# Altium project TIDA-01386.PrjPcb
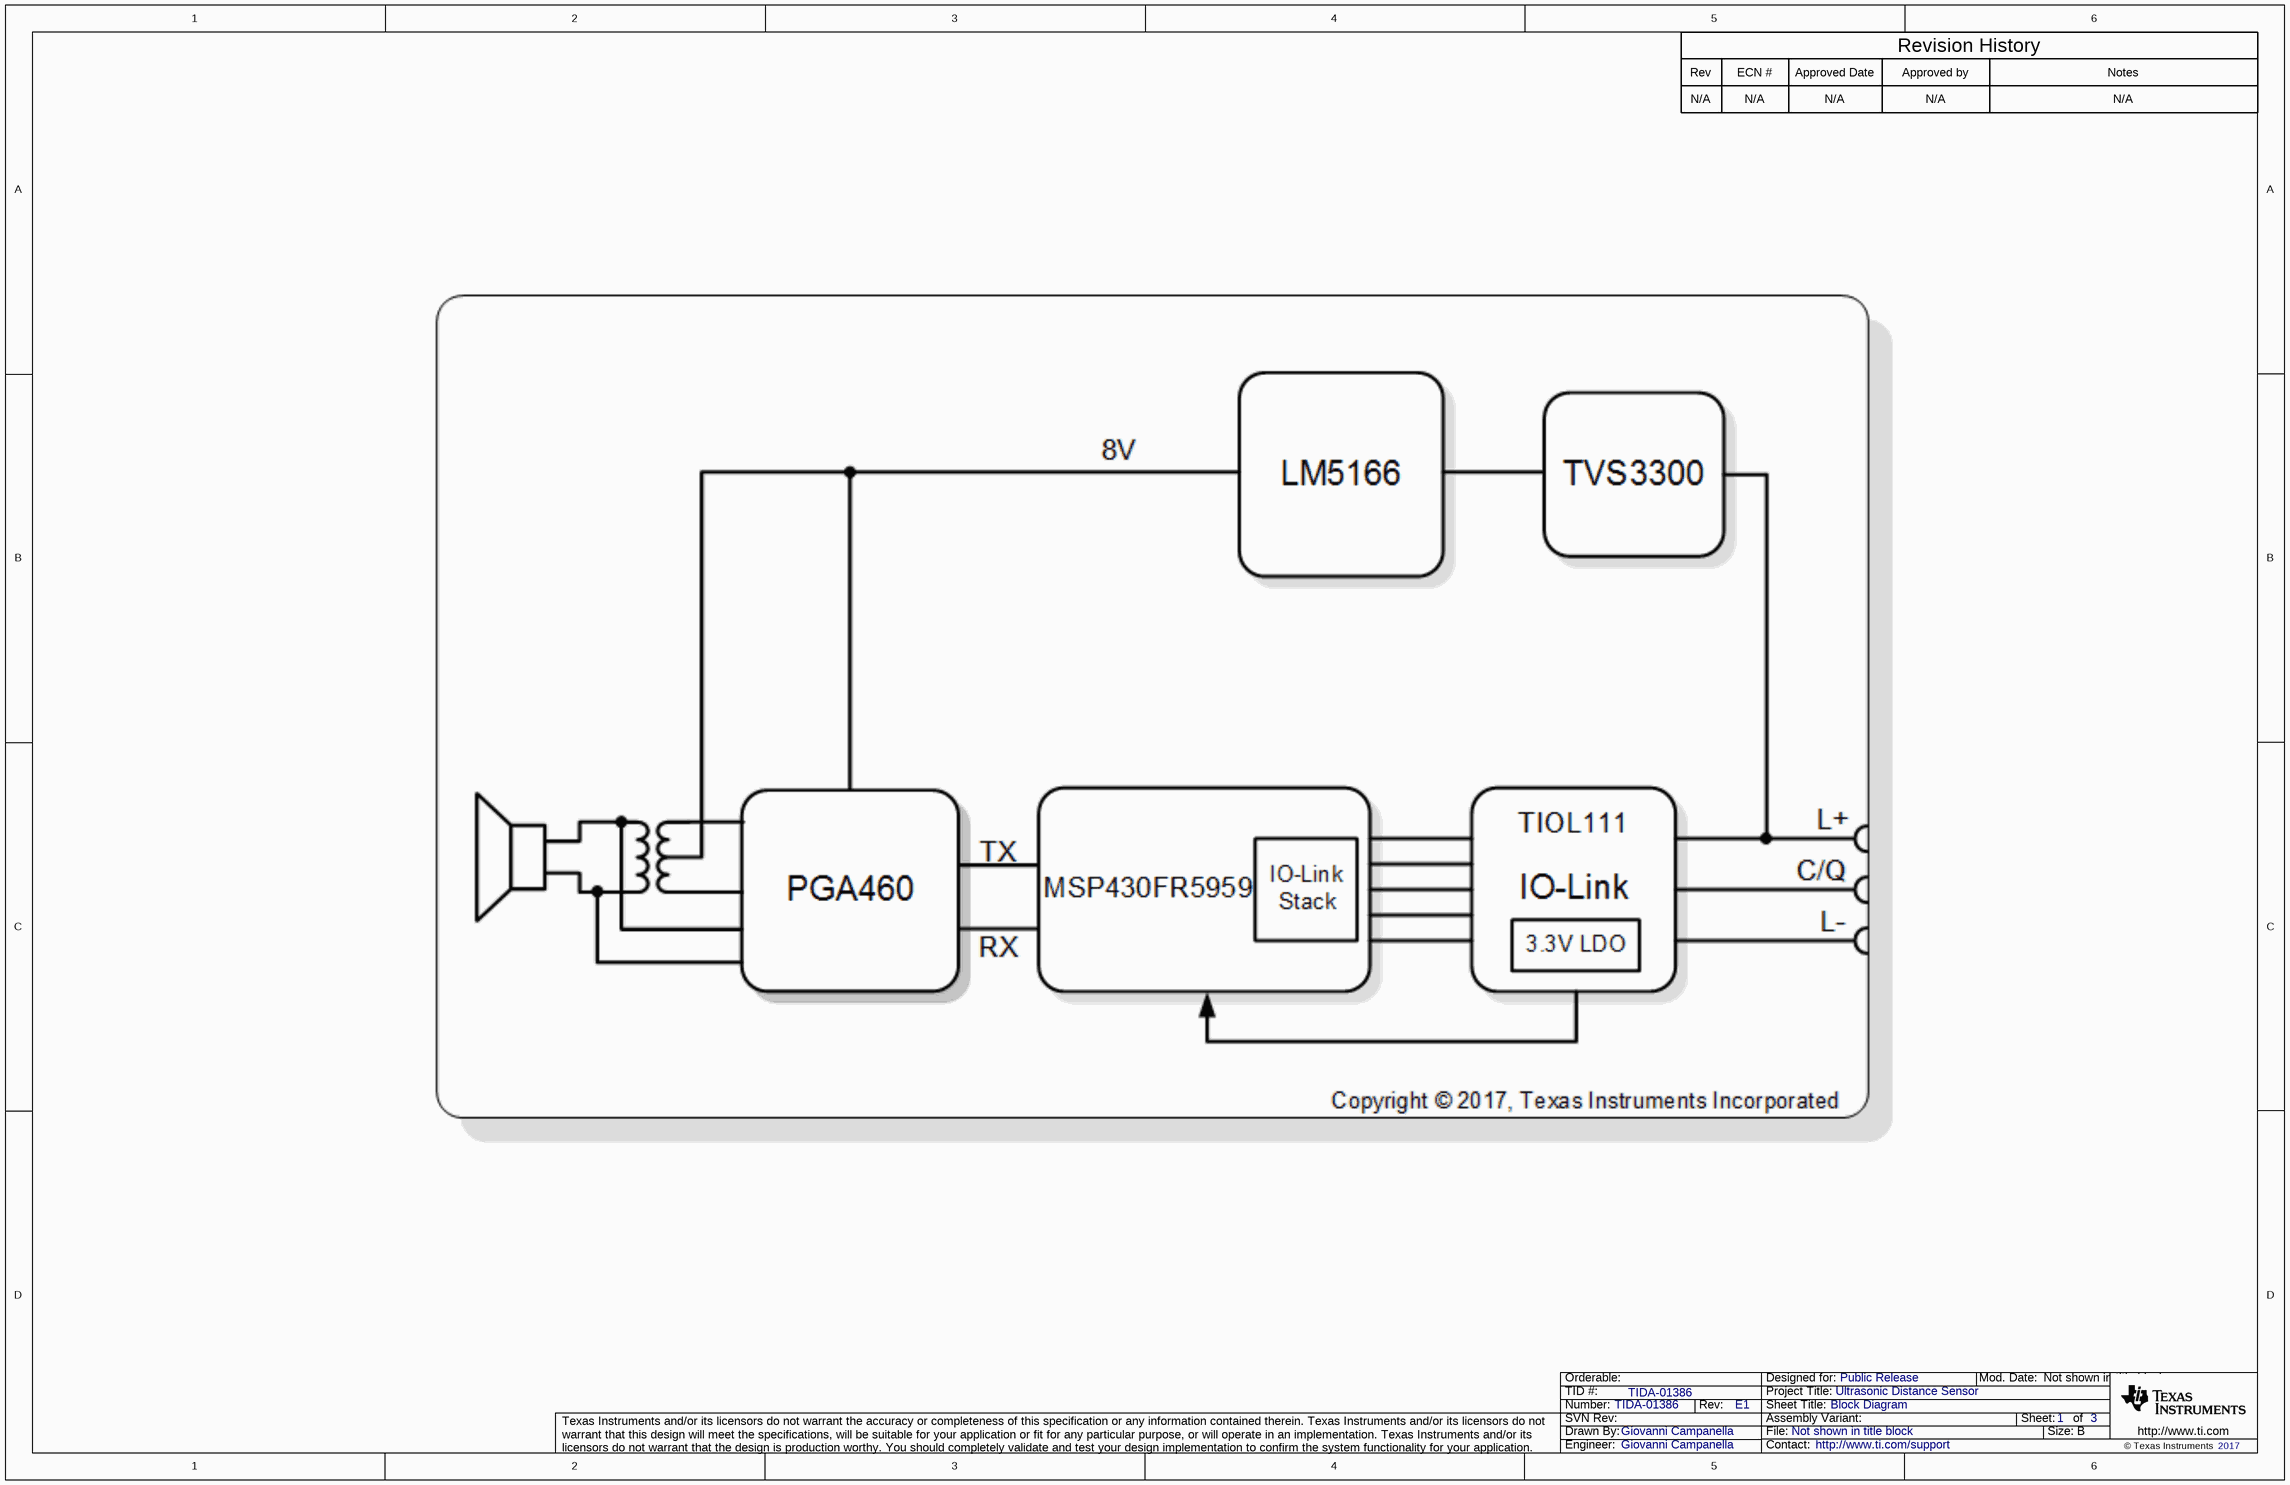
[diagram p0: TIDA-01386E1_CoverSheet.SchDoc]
TID: TIDA-01386; TechSupport: http://www.ti.com/support; SCH_Rev: E1; PRJ_Title: Ultrasonic Distance Sensor; PRJ_Number: TIDA-01386; PRJ_Engineer: Giovanni Campanella; PRJ_Customer: Public Release; PCB_Rev: E1; PCB_Layout: GCD; CopyrightYear: 2017
3 sheets, 68 parts. Net scope: flat (ports and power ports of the same name join across sheets).
Board file: TIDA-01386E1_PCB.PcbDoc
Sheets:
  TIDA-01386E1_CoverSheet.SchDoc
  TIDA-01386E1_Schematic.SchDoc
  TIDA-01386E1_Hardware.SchDoc

## Sheet TIDA-01386E1_CoverSheet.SchDoc: Block Diagram
size 431 x 279 mm; Date: Not shown in title block; ApprovedBy: Not shown in title block; CheckedBy: Not shown in title block; Author: Not shown in title block; CompanyName: Not shown in title block; DrawnBy: Giovanni Campanella; Engineer: Not shown in title block; Organization: Not shown in title block; Address1: Not shown in title block; Address2: Not shown in title block; Address3: Not shown in title block; Address4: Not shown in title block; DocumentNumber: 1; Revision: Use project parameter SCH_Rev; SheetNumber: 1; SheetTotal: 3; PageSetup: Record=PageOptions¦CenterHorizontal=True¦CenterVertical=True¦PrintScale=1.00¦XCorrection=1.00¦YCorrection=1.00¦PrintKind=0¦BorderSize=5000000¦LeftOffset=0¦BottomOffset=0¦Orientation=2¦PaperLength=1000¦PaperWidth=1000¦Scale=100¦PaperSource=15¦PrintQuality=600¦MediaType=1¦DitherType=10¦PaperKind=Letter¦PrintScaleMode=1

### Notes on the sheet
- Rev
- N/A
- ECN #
- Approved Date
- Approved by
- Revision History
- Notes

## Sheet TIDA-01386E1_Schematic.SchDoc: Schematic
size 431 x 279 mm; Date: Not shown in title block; ApprovedBy: Not shown in title block; CheckedBy: Not shown in title block; Author: Not shown in title block; CompanyName: Not shown in title block; DrawnBy: Giovanni Campanella; Engineer: Not shown in title block; Organization: Not shown in title block; Address1: Not shown in title block; Address2: Not shown in title block; Address3: Not shown in title block; Address4: Not shown in title block; DocumentNumber: 1; Revision: Use project parameter SCH_Rev; SheetNumber: 2; SheetTotal: 3; PageSetup: Record=PageOptions¦CenterHorizontal=True¦CenterVertical=True¦PrintScale=1.00¦XCorrection=1.00¦YCorrection=1.00¦PrintKind=0¦BorderSize=5000000¦LeftOffset=0¦BottomOffset=0¦Orientation=2¦PaperLength=1000¦PaperWidth=1000¦Scale=100¦PaperSource=15¦PrintQuality=600¦MediaType=1¦DitherType=10¦PaperKind=Letter¦PrintScaleMode=1
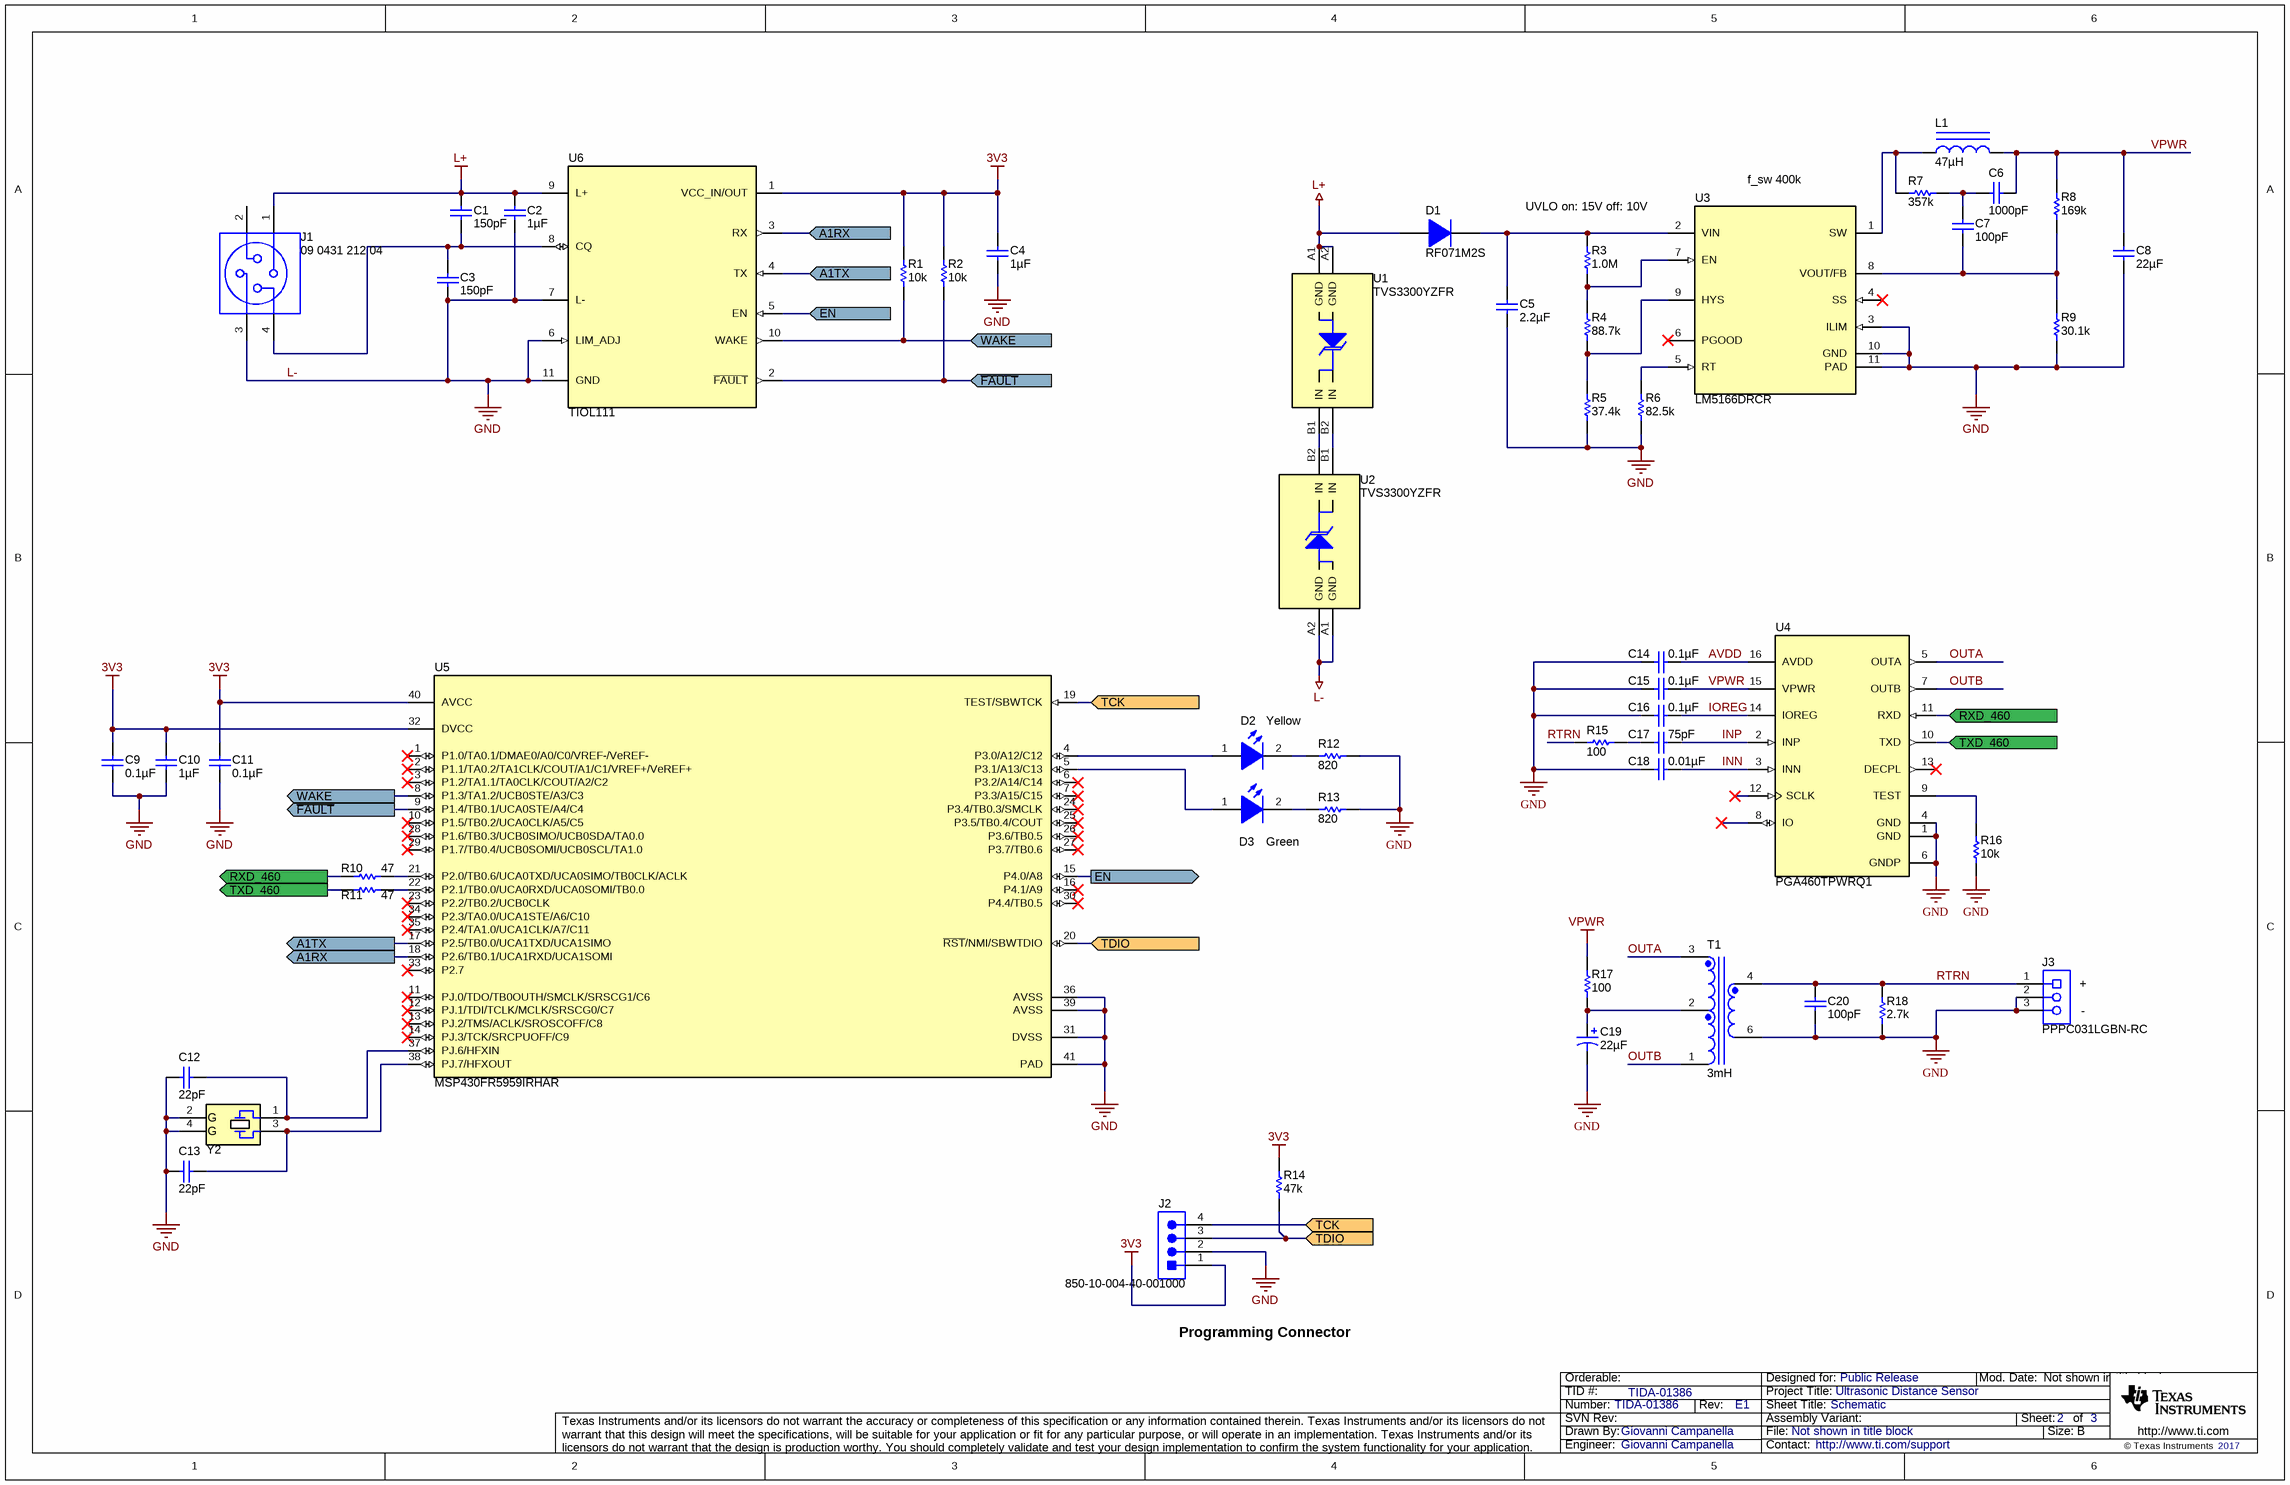
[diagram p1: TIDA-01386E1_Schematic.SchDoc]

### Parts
C1  ValueDisplayed: 150pF  [0402]  (hidden comment: 885012005062)
C2  ValueDisplayed: 1µF  [0805_HV1]  (hidden comment: CGA4J3X7S2A105K125AB)
C3  ValueDisplayed: 150pF  [0402]  (hidden comment: 885012005062)
C4  ValueDisplayed: 1µF  [0402]  (hidden comment: 885012105012)
C5  ValueDisplayed: 2.2µF  [1206_180]  (hidden comment: C3216X7S2A225K160AB)
C6  ValueDisplayed: 1000pF  [0603]  (hidden comment: 885012206083)
C7  ValueDisplayed: 100pF  [0603]  (hidden comment: 885012006057)
C8  ValueDisplayed: 22µF  [0603]  (hidden comment: C1608X5R1A226M080AC)
C9  ValueDisplayed: 0.1µF  [0402]  (hidden comment: GRM155R71E104KE14D)
C10  ValueDisplayed: 1µF  [0402]  (hidden comment: 885012105012)
C11  ValueDisplayed: 0.1µF  [0402]  (hidden comment: GRM155R71E104KE14D)
C12  ValueDisplayed: 22pF  [0402]  (hidden comment: 885012005009)
C13  ValueDisplayed: 22pF  [0402]  (hidden comment: 885012005009)
C14  ValueDisplayed: 0.1µF  [0603]  (hidden comment: C1608X7R1H104K080AA)
C15  ValueDisplayed: 0.1µF  [0603]  (hidden comment: C1608X7R1H104K080AA)
C16  ValueDisplayed: 0.1µF  [0603]  (hidden comment: C1608X7R1H104K080AA)
C17  ValueDisplayed: 75pF  [0603]  (hidden comment: GRM1885C2A750JA01D)
C18  ValueDisplayed: 0.01µF  [0603]  (hidden comment: 06031C103JAT2A)
C19  ValueDisplayed: 22µF  [CAPSMT_62_E55]  (hidden comment: EMVA350ADA220ME55G)
C20  ValueDisplayed: 100pF  [0603]  (hidden comment: C1608C0G2A101F080AA)
D1  RF071M2S  [SOD-123]
D2  value Yellow  [LY L29K_Yellow]  (hidden comment: LY L29K-J1K2-26-Z)
D3  value Green  [LG L29K_GREEN]  (hidden comment: LG L29K-G2J1-24-Z)
J1  09 0431 212 04  [Binder_713_763_Edge_ENGR-ONLY]
J2  850-10-004-40-001000  [Mill-max_850-10-004-40-001000]
J3  PPPC031LGBN-RC  [Sullins_PPxC031LGBN-RC]
L1  ValueDisplayed: 47µH  [WE-PD2-S]  (hidden comment: 744773147)
R1  ValueDisplayed: 10k  [0402]  (hidden comment: CRCW040210K0JNED)
R2  ValueDisplayed: 10k  [0402]  (hidden comment: CRCW040210K0JNED)
R3  ValueDisplayed: 1.0M  [0402]  (hidden comment: CRCW04021M00JNED)
R4  ValueDisplayed: 88.7k  [0402]  (hidden comment: CRCW040288K7FKED)
R5  ValueDisplayed: 37.4k  [0402]  (hidden comment: CRCW040237K4FKED)
R6  ValueDisplayed: 82.5k  [0402]  (hidden comment: CRCW040282K5FKED)
R7  ValueDisplayed: 357k  [0402]  (hidden comment: CRCW0402357KFKED)
R8  ValueDisplayed: 169k  [0402]  (hidden comment: CRCW0402169KFKED)
R9  ValueDisplayed: 30.1k  [0402]  (hidden comment: CRCW040230K1FKED)
R10  ValueDisplayed: 47  [0402]  (hidden comment: MCR01MZPJ470)
R11  ValueDisplayed: 47  [0402]  (hidden comment: MCR01MZPJ470)
R12  ValueDisplayed: 820  [0402]  (hidden comment: CRCW0402820RJNED)
R13  ValueDisplayed: 820  [0402]  (hidden comment: CRCW0402820RJNED)
R14  value 47k  [0402S]  (hidden comment: CRCW040247K0JNED)
R15  ValueDisplayed: 100  [0603]  (hidden comment: CRCW0603100RFKEA)
R16  ValueDisplayed: 10k  [0402]  (hidden comment: CRCW040210K0JNED)
R17  ValueDisplayed: 100  [0402]  (hidden comment: CRCW0402100RFKED)
R18  ValueDisplayed: 2.7k  [0402]  (hidden comment: CRCW04022K70JNED)
T1  ValueDisplayed: 3mH  [TDK_B78416A2232A003]  (hidden comment: B78416A2232A003)
U1  TVS3300YZFR  [YZF0004-C01]
U2  TVS3300YZFR  [YZF0004-C01]
U3  LM5166DRCR  [DRC0010J]
U4  PGA460TPWRQ1  [PW0016A_N]
U5  MSP430FR5959IRHAR  [RHA0040B]
U6  TIOL111  [TIOL111]
Y2  ABM8-14.7456MHZ-10-1-U-T  [XTAL_ABM8]  (value not drawn)

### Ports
A1RX, A1TX, EN (in), EN (out), RXD_460, TCK, TDIO, TXD_460, WAKE, ~{FAULT}

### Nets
3V3: C4.1 C9.1 C10.1 C11.1 J2.1 R1.2 R2.2 R14.2 U5.32(DVCC) U5.40(AVCC) U6.1(VCC_IN/OUT)
L+: C1.1 C2.1 D1.2(A) J1.1 U1.A1(GND) U1.A2(GND) U6.9(L+)
L-: C2.2 C3.2 C4.2 C5.2 C8.2 C9.2 C10.2 C11.2 C12.2 C13.2 C14.2 C15.2 C16.2 C18.2 C19.2(-) C20.2 J1.3 J2.2 J3.2 J3.3 R5.1 R6.1 R9.1 R12.2 R13.2 R16.1 R18.1 T1.6 U2.A1(GND) U2.A2(GND) U3.3(ILIM) U3.10(GND) U3.11(PAD) U4.1(GND) U4.4(GND) U4.6(GNDP) U5.31(DVSS) U5.36(AVSS) U5.39(AVSS) U5.41(PAD) U6.6(LIM_ADJ) U6.7(L-) U6.11(GND) Y2.2(GND) Y2.4(GND)  [also labelled GND]
VPWR: C6.1 C8.1 C15.1 L1.2 R8.2 R17.2 U4.15(VPWR)
~{FAULT}: R2.1 U5.9(P1.4/TB0.1/UCA0STE/A4/C4) U6.2(~{FAULT}) ; port ~{FAULT}
A1RX: U5.18(P2.6/TB0.1/UCA1RXD/UCA1SOMI) U6.3(RX) ; port A1RX
A1TX: U5.17(P2.5/TB0.0/UCA1TXD/UCA1SIMO) U6.4(TX) ; port A1TX
AVDD: C14.1 U4.16(AVDD)
EN: U5.15(P4.0/A8) U6.5(EN) ; port EN
INN: C18.1 U4.3(INN)
INP: C17.1 U4.2(INP)
IOREG: C16.1 U4.14(IOREG)
OUTA: T1.3 U4.5(OUTA)
OUTB: T1.1 U4.7(OUTB)
RTRN: C20.1 J3.1 R15.1 R18.2 T1.4
RXD_460: R10.1 U4.11(RXD) ; port RXD_460
TCK: J2.4 U5.19(TEST/SBWTCK) ; port TCK
TDIO: J2.3 R14.1 U5.20(~{RST}/NMI/SBWTDIO) ; port TDIO
TXD_460: R11.1 U4.10(TXD) ; port TXD_460
WAKE: R1.1 U5.8(P1.3/TA1.2/UCB0STE/A3/C3) U6.10(WAKE) ; port WAKE
NetC1_2: C1.2 C3.1 J1.4 U6.8(CQ)
NetC5_1: C5.1 D1.1(K) R3.2 U3.2(VIN)
NetC6_2: C6.2 C7.1 R7.2
NetC7_2: C7.2 R8.1 R9.2 U3.8(VOUT/FB)
NetC12_1: C12.1 U5.37(PJ.6/HFXIN) Y2.1
NetC13_1: C13.1 U5.38(PJ.7/HFXOUT) Y2.3
NetC17_2: C17.2 R15.2
NetC19_1: C19.1(+) R17.1 T1.2
NetD2_1: D2.1(A) U5.4(P3.0/A12/C12)
NetD2_2: D2.2(K) R12.1
NetD3_1: D3.1(A) U5.5(P3.1/A13/C13)
NetD3_2: D3.2(K) R13.1
NetL1_1: L1.1 R7.1 U3.1(SW)
NetR3_1: R3.1 R4.2 U3.7(EN)
NetR4_1: R4.1 R5.2 U3.9(HYS)
NetR6_2: R6.2 U3.5(RT)
NetR10_2: R10.2 U5.21(P2.0/TB0.6/UCA0TXD/UCA0SIMO/TB0CLK/ACLK)
NetR11_2: R11.2 U5.22(P2.1/TB0.0/UCA0RXD/UCA0SOMI/TB0.0)
NetR16_2: R16.2 U4.9(TEST)
NetU1_B1: U1.B1(IN) U2.B2(IN)
NetU1_B2: U1.B2(IN) U2.B1(IN)

Not connected (* = marked no-connect by the designer): J1 2; U3 4(SS)* 6(PGOOD)*; U4 8(IO)* 12(SCLK)* 13(DECPL)*; U5 1(P1.0/TA0.1/DMAE0/A0/C0/VREF-/VeREF-)* 2(P1.1/TA0.2/TA1CLK/COUT/A1/C1/VREF+/VeREF+)* 3(P1.2/TA1.1/TA0CLK/COUT/A2/C2)* 6(P3.2/A14/C14)* 7(P3.3/A15/C15)* 10(P1.5/TB0.2/UCA0CLK/A5/C5)* 11(PJ.0/TDO/TB0OUTH/SMCLK/SRSCG1/C6)* 12(PJ.1/TDI/TCLK/MCLK/SRSCG0/C7)* 13(PJ.2/TMS/ACLK/SROSCOFF/C8)* 14(PJ.3/TCK/SRCPUOFF/C9)* 16(P4.1/A9)* 23(P2.2/TB0.2/UCB0CLK)* 24(P3.4/TB0.3/SMCLK)* 25(P3.5/TB0.4/COUT)* 26(P3.6/TB0.5)* 27(P3.7/TB0.6)* 28(P1.6/TB0.3/UCB0SIMO/UCB0SDA/TA0.0)* 29(P1.7/TB0.4/UCB0SOMI/UCB0SCL/TA1.0)* 30(P4.4/TB0.5)* 33(P2.7)* 34(P2.3/TA0.0/UCA1STE/A6/C10)* 35(P2.4/TA1.0/UCA1CLK/A7/C11)*

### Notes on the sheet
- UVLO on: 15V off: 10V
- (near U3) f_sw 400k
- (near J3) +
- (near J3) -
- Programming Connector

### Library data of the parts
C1 C3 = 885012005062: CAP, CERM, 150 pF, 50 V, +/- 5%, C0G/NP0, 0402; Manufacturer: Wurth Elektronik; Polarized: N; CompType: Capacitor; Value: 150pF; U/M: EA; Cap_F: 0.00000000015; Tolerance_%: 5; Value1: Unknown; VDC_V: 50; Value2: 50V; TaMin_C: -55; TaMax_C: 125; SizeArea_mm2: 0.5; SizeAreaWB_mm2: 3; SizeX_mm: 1; SizeZ_mm: 0.6; AEC Category: Q200
C2 = CGA4J3X7S2A105K125AB: CAP, CERM, 1 µF, 100 V, +/- 10%, X7S, AEC-Q200 Grade 1, 0805; Manufacturer: TDK; Polarized: N; CompType: Capacitor; Value: 1uF; U/M: EA; Cap_F: 0.000001; Tolerance_%: 10; ESR_ohm: 0.008255; Value1: 0.008255 ohm; VDC_V: 100; Value2: 100V; IRMS_A: 2.27442; TaMin_C: -55; TaMax_C: 125; Cap_Case: 0805; SizeArea_mm2: 2.5; SizeAreaWB_mm2: 6.75; SizeX_mm: 2; SizeY_mm: 1.25; SizeZ_mm: 1.45; AEC Category: Q200; AEC Qualified: Y; AEC Grade: 1
C4 C10 = 885012105012: CAP, CERM, 1 µF, 10 V, +/- 20%, X5R, 0402; Manufacturer: Wurth Elektronik; Polarized: N; CompType: Capacitor; Value: 1uF; U/M: EA; Cap_F: 0.000001; Tolerance_%: 20; Value1: Unknown; VDC_V: 10; Value2: 10V; TaMin_C: -55; TaMax_C: 85; SizeArea_mm2: 0.5; SizeAreaWB_mm2: 3; SizeX_mm: 1; SizeZ_mm: 0.6; AEC Category: Q200
C5 = C3216X7S2A225K160AB: CAP, CERM, 2.2 µF, 100 V, +/- 10%, X7S, 1206; Manufacturer: TDK; Polarized: N; CompType: Capacitor; Value: 2.2uF; U/M: EA; Cap_F: 0.0000022; Tolerance_%: 10; ESR_ohm: 0.005718; Value1: 0.005718 ohm; VDC_V: 100; Value2: 100V; IRMS_A: 3.03632; TaMin_C: -55; TaMax_C: 125; Cap_Case: 1206; SizeArea_mm2: 5.12; SizeAreaWB_mm2: 10.92; SizeX_mm: 3.2; SizeY_mm: 1.6; SizeZ_mm: 1.8; AEC Category: Q200
C6 = 885012206083: CAP, CERM, 1000 pF, 50 V, +/- 10%, X7R, 0603; Manufacturer: Wurth Elektronik; Polarized: N; CompType: Capacitor; Value: 1000pF; U/M: EA; Cap_F: 0.000000001; Tolerance_%: 10; Value1: Unknown; VDC_V: 50; Value2: 50V; TaMin_C: -55; TaMax_C: 125; SizeArea_mm2: 1.28; SizeAreaWB_mm2: 4.68; SizeX_mm: 1.6; SizeY_mm: 0.8; SizeZ_mm: 1; AEC Category: Q200
C7 = 885012006057: CAP, CERM, 100 pF, 50 V, +/- 5%, C0G/NP0, 0603; Manufacturer: Wurth Elektronik; Polarized: N; CompType: Capacitor; Value: 100pF; U/M: EA; Cap_F: 0.0000000001; Tolerance_%: 5; Value1: Unknown; VDC_V: 50; Value2: 50V; TaMin_C: -55; TaMax_C: 125; SizeArea_mm2: 1.28; SizeAreaWB_mm2: 4.68; SizeX_mm: 1.6; SizeY_mm: 0.8; SizeZ_mm: 1; AEC Category: Q200
C8 = C1608X5R1A226M080AC: CAP, CERM, 22 µF, 10 V, +/- 20%, X5R, 0603; Manufacturer: TDK; Polarized: N; CompType: Capacitor; Value: 22uF; U/M: EA; Cap_F: 0.000022; Tolerance_%: 20; ESR_ohm: 0.00371; Value1: 0.00371 ohm; VDC_V: 10; Value2: 10V; IRMS_A: 2.69936; TaMin_C: -55; TaMax_C: 85; SizeArea_mm2: 1.28; SizeAreaWB_mm2: 4.68; SizeX_mm: 1.6; SizeY_mm: 0.8; SizeZ_mm: 1; AEC Category: Q200; Green_Lifecycle: Active; Green_REACh: Passed
C9 C11 = GRM155R71E104KE14D: CAP, CERM, 0.1 µF, 25 V, +/- 10%, X7R, 0402; Manufacturer: MuRata; Polarized: N; CompType: Capacitor; Value: 0.1uF; U/M: EA; Cap_F: 0.0000001; Tolerance_%: 10; Value1: Unknown; VDC_V: 25; Value2: 25V; TaMin_C: -55; TaMax_C: 125; AEC Category: Q200
C12 C13 = 885012005009: CAP, CERM, 22 pF, 10 V, +/- 5%, C0G/NP0, 0402; Manufacturer: Wurth Elektronik; Polarized: N; CompType: Capacitor; Value: 22pF; U/M: EA; Cap_F: 0.000000000022; Tolerance_%: 5; Value1: Unknown; VDC_V: 10; Value2: 10V; TaMin_C: -55; TaMax_C: 125; SizeArea_mm2: 0.5; SizeAreaWB_mm2: 3; SizeX_mm: 1; SizeZ_mm: 0.6; AEC Category: Q200
C14-C16 = C1608X7R1H104K080AA: CAP, CERM, 0.1 µF, 50 V, +/- 10%, X7R, 0603; Manufacturer: TDK; Polarized: N; CompType: Capacitor; Value: 0.1uF; U/M: EA; Cap_F: 0.0000001; Tolerance_%: 10; Value1: Unknown; VDC_V: 50; Value2: 50V; TaMin_C: -55; TaMax_C: 125; AEC Category: Q200
C17 = GRM1885C2A750JA01D: CAP, CERM, 75 pF, 100 V, +/- 5%, C0G/NP0, 0603; Manufacturer: MuRata; Polarized: N; CompType: Capacitor; Value: 75pF; U/M: EA; Cap_F: 0.000000000075; Tolerance_%: 5; Value1: Unknown; VDC_V: 100; Value2: 100V; TaMin_C: -55; TaMax_C: 125; SizeArea_mm2: 1.28; SizeAreaWB_mm2: 4.68; SizeX_mm: 1.6; SizeY_mm: 0.8; SizeZ_mm: 1; AEC Category: Q200
C18 = 06031C103JAT2A: CAP, CERM, 0.01 µF, 100 V, +/- 5%, X7R, 0603; Manufacturer: AVX; Polarized: N; CompType: Capacitor; Value: 0.01uF; U/M: EA; Cap_F: 0.00000001; Tolerance_%: 5; ESR_ohm: 0.098; Value1: 0.098 ohm; VDC_V: 100; Value2: 100V; TaMin_C: -55; TaMax_C: 125; SizeArea_mm2: 1.28; SizeAreaWB_mm2: 4.68; SizeX_mm: 1.6; SizeY_mm: 0.8; SizeZ_mm: 1; AEC Category: Q200; Green_Lifecycle: Active; Green_REACh: Passed
C19 = EMVA350ADA220ME55G: CAP, AL, 22 µF, 35 V, +/- 20%, SMD; Manufacturer: Chemi-Con; Polarized: Y; CompType: Capacitor; Value: 22uF; U/M: EA; Cap_F: 0.000022; Tolerance_%: 20; Value1: Unknown; VDC_V: 35; Value2: 35V; IRMS_A: 0.041; TaMin_C: -40; TaMax_C: 85; Cap_Case: E55; SizeAreaWB_mm2: 53.29; SizeArea_mm2: 28.09; SizeX_mm: 5.3; SizeZ_mm: 5.2; AEC Category: Q200
C20 = C1608C0G2A101F080AA: CAP, CERM, 100 pF, 100 V, +/- 1%, C0G/NP0, 0603; Manufacturer: TDK; Polarized: N; CompType: Capacitor; Value: 100pF; U/M: EA; Cap_F: 0.0000000001; Tolerance_%: 1; Value1: Unknown; VDC_V: 100; Value2: 100V; TaMin_C: -55; TaMax_C: 125; SizeArea_mm2: 1.28; SizeAreaWB_mm2: 4.68; SizeX_mm: 1.6; SizeY_mm: 0.8; AEC Category: Q200; Green_Lifecycle: NRND; Green_REACh: Passed
D1 = RF071M2S: Diode, Ultrafast, 200 V, 1 A, SOD-123; Manufacturer: Rohm; U/M: EA; Vf_V: 0.85; Value: 200V; Value1: 1A; Value2: 0.85V; Io_A: 1; Vr_V: 200; TJmax_C: 150; SizeAreaWB_mm2: 13.095; SizeArea_mm2: 6.545; SizeX_mm: 3.85; SizeY_mm: 1.7; SizeZ_mm: 1.35; AEC Category: Q101; Green_Lifecycle: Not Set; Green_REACh: Incomplete
D2 = LY L29K-J1K2-26-Z: LED, Yellow, SMD; Manufacturer: OSRAM; Vf_V: 1.8; Value2: 1.8V; Io_A: 0.002; Tjmax_C: 110; Value1: W; U/M: EA; Green_Lifecycle: Active; Green_REACh: Passed
D3 = LG L29K-G2J1-24-Z: LED, Green, SMD; Manufacturer: OSRAM; Vf_V: 1.7; Value2: 1.7V; Io_A: 0.002; Tjmax_C: 110; Value1: W; U/M: EA; Green_Lifecycle: Not Set; Green_REACh: Incomplete
J1 = 09 0431 212 04: M12 Socket, 4Pos, TH; Manufacturer: Binder-Connector; SymbolCreator: x0208325
J2 = 850-10-004-40-001000: Header, 50mil, 4x1, Gold, R/A, SMT; Manufacturer: Mill-Max; SymbolCreator: a0412235
J3 = PPPC031LGBN-RC: Receptacle, 2.54 mm, 3x1, Gold, R/A, TH; Manufacturer: Sullins Connector Solutions; SymbolCreator: a0412235
L1 = 744773147: Inductor, Shielded Drum Core, Ferrite, 47 µH, 0.68 A, 0.844 ohm, SMD; Manufacturer: Wurth Elektronik; Value: 47uH; Ind_H: 47.0E-6; Imax_A: 0.68; Irms: 0.68A @ 40C rise; Isat: 0.77A @ 10% inductance drop; DCR_ohm: 0.844; Value2: 0.68A; SizeAreaWB_mm2: 27.5; SizeArea_mm2: 18; SizeX_mm: 4; SizeY_mm: 4.5; SizeZ_mm: 3.2; AEC Category: Q200; Green_Lifecycle: Active; Green_REACh: Passed
R1 R2 R16 = CRCW040210K0JNED: RES, 10 k, 5%, 0.063 W, 0402; Manufacturer: Vishay-Dale; CompType: Resistor; Value: 10k; Res_ohm: 10000; Value_Code: 10k0; Tolerance_%: 5; Power_W: 0.063; Value2: 0.063W; VDC_V: 50; TempCo: 200 ppm/C; SizeArea_mm2: 0.5; SizeX_mm: 1; SizeZ_mm: 0.6; EIA_Code: E24; U/M: EA; AEC Category: Q200
R3 = CRCW04021M00JNED: RES, 1.0 M, 5%, 0.063 W, 0402; Manufacturer: Vishay-Dale; CompType: Resistor; Value: 1.0Meg; Res_ohm: 1000000; Value_Code: 1M00; Tolerance_%: 5; Power_W: 0.063; Value2: 0.063W; VDC_V: 50; TempCo: 200 ppm/C; SizeArea_mm2: 0.5; SizeX_mm: 1; SizeZ_mm: 0.6; EIA_Code: E24; U/M: EA; AEC Category: Q200
R4 = CRCW040288K7FKED: RES, 88.7 k, 1%, 0.063 W, 0402; Manufacturer: Vishay-Dale; CompType: Resistor; Value: 88.7k; Res_ohm: 88700; Value_Code: 88k7; Tolerance_%: 1; Power_W: 0.063; Value2: 0.063W; VDC_V: 50; TempCo: 100 ppm/C; SizeArea_mm2: 0.5; SizeZ_mm: 0.6; EIA_Code: E96; U/M: EA; AEC Category: Q200
R5 = CRCW040237K4FKED: RES, 37.4 k, 1%, 0.063 W, 0402; Manufacturer: Vishay-Dale; CompType: Resistor; Value: 37.4k; Res_ohm: 37400; Value_Code: 37k4; Tolerance_%: 1; Power_W: 0.063; Value2: 0.063W; VDC_V: 50; TempCo: 100 ppm/C; SizeArea_mm2: 0.5; SizeZ_mm: 0.6; EIA_Code: E96; U/M: EA; AEC Category: Q200
R6 = CRCW040282K5FKED: RES, 82.5 k, 1%, 0.063 W, AEC-Q200 Grade 0, 0402; Manufacturer: Vishay-Dale; CompType: Resistor; Value: 82.5k; Res_ohm: 82500; Value_Code: 82k5; Tolerance_%: 1; Power_W: 0.063; Value2: 0.063W; VDC_V: 50; TempCo: 100 ppm/C; SizeArea_mm2: 0.5; SizeZ_mm: 0.6; EIA_Code: E96; U/M: EA; AEC Category: Q200; AEC Qualified: Y; AEC Grade: 0
R7 = CRCW0402357KFKED: RES, 357 k, 1%, 0.063 W, 0402; Manufacturer: Vishay-Dale; CompType: Resistor; Value: 357k; Res_ohm: 357000; Tolerance_%: 1; Power_W: 0.063; Value2: 0.063W; VDC_V: 50; TempCo: 100 ppm/C; SizeArea_mm2: 0.5; SizeZ_mm: 0.6; EIA_Code: E96; U/M: EA; AEC Category: Q200
R8 = CRCW0402169KFKED: RES, 169 k, 1%, 0.063 W, 0402; Manufacturer: Vishay-Dale; CompType: Resistor; Value: 169k; Res_ohm: 169000; Tolerance_%: 1; Power_W: 0.063; Value2: 0.063W; VDC_V: 50; TempCo: 100 ppm/C; SizeArea_mm2: 0.5; SizeZ_mm: 0.6; EIA_Code: E96; U/M: EA; AEC Category: Q200
R9 = CRCW040230K1FKED: RES, 30.1 k, 1%, 0.063 W, 0402; Manufacturer: Vishay-Dale; CompType: Resistor; Value: 30.1k; Res_ohm: 30100; Value_Code: 30k1; Tolerance_%: 1; Power_W: 0.063; Value2: 0.063W; VDC_V: 50; TempCo: 100 ppm/C; SizeArea_mm2: 0.5; SizeZ_mm: 0.6; EIA_Code: E96; U/M: EA; AEC Category: Q200
R10 R11 = MCR01MZPJ470: RES, 47, 5%, 0.063 W, 0402; Manufacturer: Rohm; CompType: Resistor; Value: 47; Value_Code: 47R0; Tolerance_%: 5; Power_W: 0.063; Value2: 0.063W; TempCo: 200 ppm/C; SizeArea_mm2: 0.5; SizeX_mm: 1; SizeZ_mm: 0.6; EIA_Code: E24; U/M: EA; AEC Category: Q200; AEC Qualified: N
R12 R13 = CRCW0402820RJNED: RES, 820, 5%, 0.063 W, 0402; Manufacturer: Vishay-Dale; CompType: Resistor; Value: 820; Value_Code: 820R; Tolerance_%: 5; Power_W: 0.063; Value2: 0.063W; VDC_V: 50; TempCo: 200 ppm/C; SizeArea_mm2: 0.5; SizeX_mm: 1; SizeZ_mm: 0.6; EIA_Code: E24; U/M: EA; AEC Category: Q200
R14 = CRCW040247K0JNED: RES, 47k ohm, 5%, 0.063W, 0402; Manufacturer: Vishay-Dale; CompType: Resistor; Res_ohm: 47000; Value_Code: 47k0; Tolerance_%: 5; Power_W: 0.063; VDC_V: 50; TempCo: 200 ppm/C; EIA_Code: E24; U/M: EA
R15 = CRCW0603100RFKEA: RES, 100, 1%, 0.1 W, 0603; Manufacturer: Vishay-Dale; CompType: Resistor; Value: 100; Value_Code: 100R; Tolerance_%: 1; Power_W: 0.1; Value2: 0.1W; VDC_V: 75; TempCo: 100 ppm/C; SizeArea_mm2: 1.28; SizeX_mm: 1.6; SizeY_mm: 0.8; EIA_Code: E96; U/M: EA; AEC Category: Q200
R17 = CRCW0402100RFKED: RES, 100, 1%, 0.063 W, 0402; Manufacturer: Vishay-Dale; CompType: Resistor; Value: 100; Value_Code: 100R; Tolerance_%: 1; Power_W: 0.063; Value2: 0.063W; VDC_V: 50; TempCo: 100 ppm/C; SizeArea_mm2: 0.5; SizeZ_mm: 0.6; EIA_Code: E96; U/M: EA; AEC Category: Q200
R18 = CRCW04022K70JNED: RES, 2.7 k, 5%, 0.063 W, 0402; Manufacturer: Vishay-Dale; CompType: Resistor; Value: 2.7k; Res_ohm: 2700; Value_Code: 2k70; Tolerance_%: 5; Power_W: 0.063; Value2: 0.063W; VDC_V: 50; TempCo: 200 ppm/C; SizeArea_mm2: 0.5; SizeX_mm: 1; SizeZ_mm: 0.6; EIA_Code: E24; U/M: EA; AEC Category: Q200
T1 = B78416A2232A003: Transformer, 3 mH, SMT; Manufacturer: TDK; SymbolCreator: Altium; Value: 3mH; Lp: 3000; Ns1toNp: 0.1188
U1 U2 = TVS3300YZFR: 33V Precision Surge Protection Clamp, YZF0004-C01 (DSBGA-4); Alternate PartNumber: TVS3300YZFT; Manufacturer: Texas Instruments; SymbolCreator: Altium; SizeArea_mm2: 1.1984; SizeAreaWB_mm2: 4.3884; SizeX_mm: 1.12; SizeY_mm: 1.07; SizeZ_mm: 0.625; CompType: IC; U/M: EA
U3 = LM5166DRCR: 3.0-V to 65-V Input, 500-mA Synchronous Buck Converter with Ultra-Low IQ, DRC0010J (VSON-10); Alternate PartNumber: LM5166DRCT; Manufacturer: Texas Instruments; SymbolCreator: a0411947; SizeArea_mm2: 9; SizeAreaWB_mm2: 16; SizeX_mm: 3; SizeZ_mm: 1; CompType: IC; U/M: EA
U4 = PGA460TPWRQ1: PGA460TPWRQ1, PW0016A; Manufacturer: Texas Instruments; SymbolCreator: Altium; SizeArea_mm2: 32; SizeAreaWB_mm2: 58.8; SizeX_mm: 6.4; SizeY_mm: 5; SizeZ_mm: 1.2; CompType: IC; U/M: EA
U5 = MSP430FR5959IRHAR: MSP430FR5959 16 MHz Ultra-Low-Power Microcontroller featuring 64 KB FRAM, 2 KB SRAM, 33 IO, RHA0040B (VQFN-40); Alternate PartNumber: MSP430FR5959IRHAT; Manufacturer: Texas Instruments; SymbolCreator: Altium; SizeArea_mm2: 37.8225; SizeAreaWB_mm2: 66.4225; SizeX_mm: 6.15; SizeZ_mm: 1; CompType: IC; U/M: EA
U6 = TIOL111: IO-Link Device Transceiver with Integrated Surge Protection, TIOL111 (WSON-10); Manufacturer: Texas Instruments; SymbolCreator: Altium; SizeArea_mm2: 7.5; SizeAreaWB_mm2: 14; SizeX_mm: 3; SizeY_mm: 2.5; SizeZ_mm: 1; CompType: IC; U/M: EA
Y2 = CMP-0076763-1: Crystal, 14.7456 MHz, 10 pF, SMD; Manufacturer: Abracon Corporation; Frequency Stability: ±10 ppm; TaMax_C: 60°C; TaMin_C: -10°C; U/M: EA

## Sheet TIDA-01386E1_Hardware.SchDoc: Hardware
size 431 x 279 mm; Date: Not shown in title block; ApprovedBy: Not shown in title block; CheckedBy: Not shown in title block; Author: Not shown in title block; CompanyName: Not shown in title block; DrawnBy: Giovanni Campanella; Engineer: Not shown in title block; Organization: Not shown in title block; Address1: Not shown in title block; Address2: Not shown in title block; Address3: Not shown in title block; Address4: Not shown in title block; DocumentNumber: 1; Revision: Use project parameter SCH_Rev; SheetNumber: 3; SheetTotal: 3; PageSetup: Record=PageOptions¦CenterHorizontal=True¦CenterVertical=True¦PrintScale=1.00¦XCorrection=1.00¦YCorrection=1.00¦PrintKind=0¦BorderSize=5000000¦LeftOffset=0¦BottomOffset=0¦Orientation=2¦PaperLength=1000¦PaperWidth=1000¦Scale=100¦PaperSource=15¦PrintQuality=600¦MediaType=1¦DitherType=10¦PaperKind=Letter¦PrintScaleMode=1
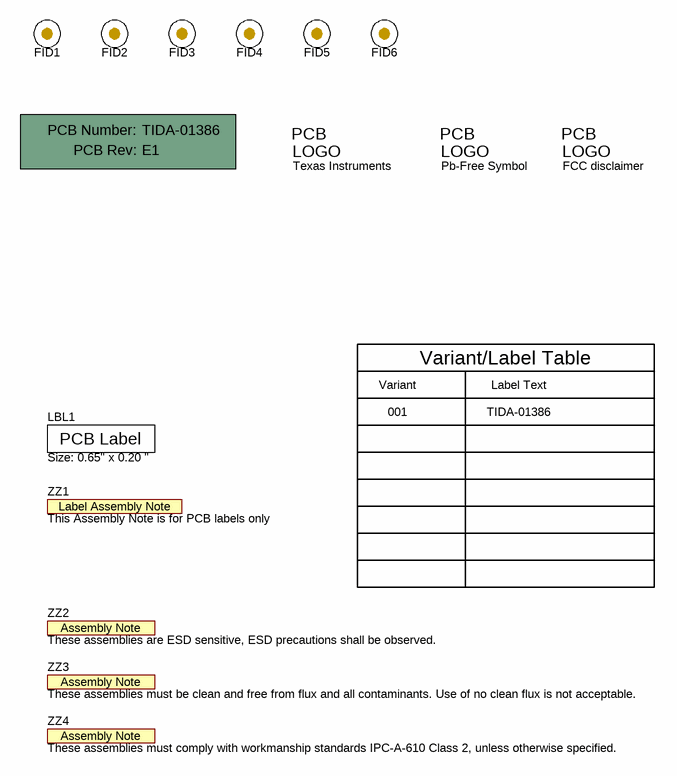
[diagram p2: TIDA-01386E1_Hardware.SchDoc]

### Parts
!PCB  Printed Circuit Board  (value not drawn)  (mechanical)
FID1  Fiducial  [Fiducial10-20]  (value not drawn)
FID2  Fiducial  [Fiducial10-20]  (value not drawn)
FID3  Fiducial  [Fiducial10-20]  (value not drawn)
FID4  Fiducial  [Fiducial10-20]  (value not drawn)
FID5  Fiducial  [Fiducial10-20]  (value not drawn)
FID6  Fiducial  [Fiducial10-20]  (value not drawn)
LBL1  Size: 0.65" x 0.20 "  [Label_650x200]
Logo1  Texas Instruments  [TI_Stacked_Overlay_Small]  (no BOM)
Logo2  Pb-Free Symbol  [Pb-Free_Overlay_Small]  (no BOM)
Logo3  FCC disclaimer  [FCC_disclaimer]  (no BOM)
ZZ1  This Assembly Note is for PCB labels only  [AssemblyNoteLabel]  (no BOM)
ZZ2  These assemblies are ESD sensitive, ESD precautions shall be observed.  [AssemblyNote]  (no BOM)
ZZ3  These assemblies must be clean and free from flux and all contaminants. Use of no clean flux is not acceptable.  [AssemblyNote]  (no BOM)
ZZ4  These assemblies must comply with workmanship standards IPC-A-610 Class 2, unless otherwise specified.  [AssemblyNote]  (no BOM)

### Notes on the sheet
- Variant
- Variant/Label Table
- Label Text
- 001
- TIDA-01386

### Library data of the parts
!PCB = PCB: Manufacturer: Any; PartNumber: TIDA-01386; SymbolCreator: a0412235
FID1-FID6 = Fiducial: Fiducial mark.  There is nothing to buy or mount.; SymbolCreator: codlsc
LBL1 = THT-14-423-10: Thermal Transfer Printable Labels, 0.650" W x 0.200" H - 10,000 per roll; Manufacturer: Brady; SymbolCreator: a0412235; CompType: Label
Logo1 = TI_Logo: Texas Instrument Corporate Signature; SymbolCreator: codlsc
Logo2 = Pb-Free: SymbolCreator: a0412235
Logo3 = FCC_disclaimer: SymbolCreator: codlsc
ZZ1 = AssemblyNoteLabel: SymbolCreator: a0412235
ZZ2-ZZ4 = AssemblyNote: SymbolCreator: codlsc

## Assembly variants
001: not fitted FID1 FID2 FID3 FID4 FID5 FID6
